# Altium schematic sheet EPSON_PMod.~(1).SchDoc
size A4
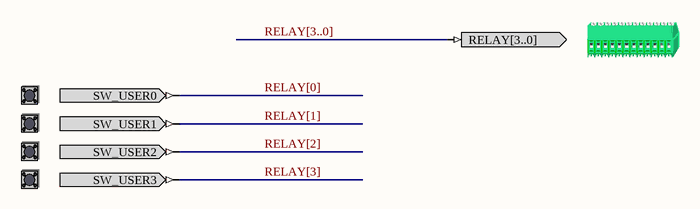
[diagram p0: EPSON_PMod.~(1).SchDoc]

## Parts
(Parts that share a designator on the sheet are numbered #1, #2 ... from top to bottom, then left to right.)
?#1  RELAYCNTR  (value not drawn)
?#2  USER_BUTTON0  (value not drawn)
?#3  USER_BUTTON1  (value not drawn)
?#4  USER_BUTTON2  (value not drawn)
?#5  USER_BUTTON3  (value not drawn)

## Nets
RELAY[0]: ?#2.SW_USER0
RELAY[1]: ?#3.SW_USER1
RELAY[2]: ?#4.SW_USER2
RELAY[3]: ?#5.SW_USER3

Not connected (* = marked no-connect by the designer): ?#1 RELAY[3..0]

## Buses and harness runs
bus RELAY[3..0]

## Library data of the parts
?#1 = RELAYCNTR: RELAY; PortComponent: True
?#2 = USER_BUTTON0: Generic User Button; PortComponent: True
?#3 = USER_BUTTON1: Generic User Button; PortComponent: True
?#4 = USER_BUTTON2: Generic User Button; PortComponent: True
?#5 = USER_BUTTON3: Generic User Button; PortComponent: True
